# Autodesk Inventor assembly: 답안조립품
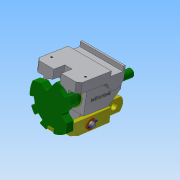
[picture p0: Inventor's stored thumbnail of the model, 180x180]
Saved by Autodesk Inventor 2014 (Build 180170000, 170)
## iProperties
Created: 2016-11
Part Number: 답안조립품
Document SubType Name: Assembly
Designer: net
Author: net
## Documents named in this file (8)
- C:\Users\net\Desktop\461107V1018\답안조립품.iam
- C:\Users\net\Desktop\461107V1018\답안조립품.ipt
- C:\Users\net\Desktop\461107V1018\분할축.ipt
- C:\Users\net\Desktop\461107V1018\부시.ipt
- C:\Users\net\Desktop\461107V1018\분할대.ipt
- C:\Users\net\Desktop\461107V1018\클레비스핀.ipt
- C:\Users\net\Desktop\461107V1018\와셔.ipt
- C:\Users\net\Desktop\461107V1018\원통형핀.ipt
